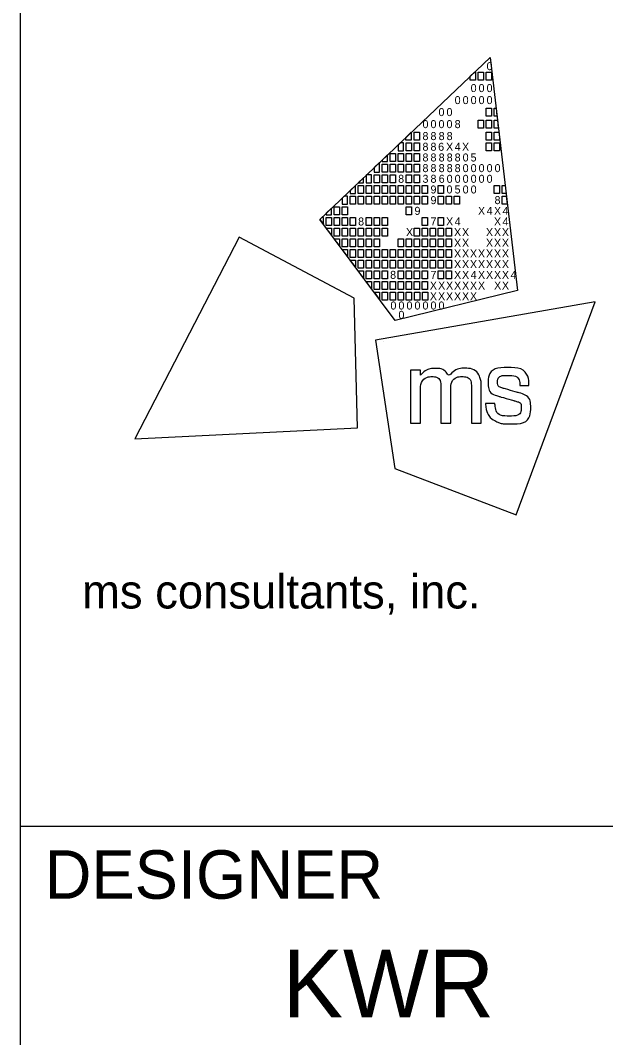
# Model space of a CAD drawing. Extents: x -0.2 to 34, y -3.5 to 18.5.
# Drawn here: x 32 to 33.207, y -1.472 to 0.627 of the extents above; entities that cross this region are included whole.
import ezdxf

# ---------------------------------------------------------------- set-up
doc = ezdxf.new("R2010")
doc.units = 0
doc.layers.add('SH_Border', color=7, linetype='Continuous')
doc.layers.add('SH_Data', color=7, linetype='Continuous')

msp = doc.modelspace()

# ---------------------------------------------------------------- linework, layer by layer
at = {"layer": 'SH_Border'}
for p, q in [((32, -3.0354), (32, 17.9646)), ((32, -1.0354), (33.5, -1.0354))]:
    msp.add_line(p, q, dxfattribs=at)
at = {"layer": 'SH_Data'}
for p, q in [((32.6175, 0.2165), (32.9688, 0.5507)), ((32.9688, 0.5507), (32.9688, 0.5507)), ((32.9688, 0.5507), (33.0253, 0.0697)), ((32.773, 0.0076), (32.6175, 0.2165)), ((33.0253, 0.0697), (32.773, 0.0076)), ((32.75, -0.0354), (32.75, -0.0354))]:
    msp.add_line(p, q, dxfattribs=at)
for points in [[(32.9279, 0.5118), (32.9369, 0.5203), (32.9389, 0.5203), (32.9389, 0.5038), (32.9279, 0.5038)], [(32.9444, 0.5203), (32.9554, 0.5203), (32.9554, 0.5038), (32.9444, 0.5038)], [(32.9609, 0.5203), (32.9719, 0.5203), (32.9719, 0.5038), (32.9609, 0.5038)], [(32.9606, 0.446), (32.9716, 0.446), (32.9716, 0.4295), (32.9606, 0.4295)], [(32.9771, 0.446), (32.9811, 0.446), (32.983, 0.4295), (32.9771, 0.4295)], [(32.9441, 0.4213), (32.9551, 0.4213), (32.9551, 0.4047), (32.9441, 0.4047)], [(32.9606, 0.4213), (32.9716, 0.4213), (32.9716, 0.4047), (32.9606, 0.4047)], [(32.9771, 0.4213), (32.984, 0.4213), (32.9859, 0.4047), (32.9771, 0.4047)], [(32.7953, 0.3857), (32.8064, 0.3961), (32.8064, 0.38), (32.7953, 0.38)], [(32.8123, 0.3965), (32.8233, 0.3965), (32.8233, 0.38), (32.8123, 0.38)], [(32.9606, 0.3965), (32.9716, 0.3965), (32.9716, 0.38), (32.9606, 0.38)], [(32.9771, 0.3965), (32.9869, 0.3965), (32.9881, 0.3864), (32.9881, 0.38), (32.9771, 0.38)], [(32.7958, 0.3745), (32.8068, 0.3745), (32.8068, 0.358), (32.7958, 0.358)], [(32.8123, 0.3745), (32.8233, 0.3745), (32.8233, 0.358), (32.8123, 0.358)], [(32.9606, 0.3745), (32.9716, 0.3745), (32.9716, 0.358), (32.9606, 0.358)], [(32.9771, 0.3745), (32.9881, 0.3745), (32.9881, 0.358), (32.9771, 0.358)], [(32.7627, 0.3524), (32.7737, 0.3524), (32.7737, 0.3359), (32.7627, 0.3359)], [(32.7793, 0.3524), (32.7903, 0.3524), (32.7903, 0.3359), (32.7793, 0.3359)], [(32.7958, 0.3524), (32.8068, 0.3524), (32.8068, 0.3359), (32.7958, 0.3359)], [(32.8123, 0.3524), (32.8233, 0.3524), (32.8233, 0.3359), (32.8123, 0.3359)], [(32.7462, 0.3304), (32.7572, 0.3304), (32.7572, 0.3139), (32.7462, 0.3139)], [(32.7627, 0.3304), (32.7737, 0.3304), (32.7737, 0.3139), (32.7627, 0.3139)], [(32.7793, 0.3304), (32.7903, 0.3304), (32.7903, 0.3139), (32.7793, 0.3139)], [(32.7958, 0.3304), (32.8068, 0.3304), (32.8068, 0.3139), (32.7958, 0.3139)], [(32.8123, 0.3304), (32.8233, 0.3304), (32.8233, 0.3139), (32.8123, 0.3139)], [(32.7297, 0.3084), (32.7407, 0.3084), (32.7407, 0.2919), (32.7297, 0.2919)], [(32.7462, 0.3084), (32.7572, 0.3084), (32.7572, 0.2919), (32.7462, 0.2919)], [(32.7627, 0.3084), (32.7737, 0.3084), (32.7737, 0.2919), (32.7627, 0.2919)], [(32.7958, 0.3084), (32.8068, 0.3084), (32.8068, 0.2919), (32.7958, 0.2919)], [(32.8123, 0.3084), (32.8233, 0.3084), (32.8233, 0.2919), (32.8123, 0.2919)], [(32.6967, 0.2864), (32.7077, 0.2864), (32.7077, 0.2699), (32.6967, 0.2699)], [(32.7132, 0.2864), (32.7242, 0.2864), (32.7242, 0.2699), (32.7132, 0.2699)], [(32.7297, 0.2864), (32.7407, 0.2864), (32.7407, 0.2699), (32.7297, 0.2699)], [(32.7462, 0.2864), (32.7572, 0.2864), (32.7572, 0.2699), (32.7462, 0.2699)], [(32.7627, 0.2864), (32.7737, 0.2864), (32.7737, 0.2699), (32.7627, 0.2699)], [(32.7793, 0.2864), (32.7903, 0.2864), (32.7903, 0.2699), (32.7793, 0.2699)], [(32.7958, 0.2864), (32.8068, 0.2864), (32.8068, 0.2699), (32.7958, 0.2699)], [(32.8123, 0.2864), (32.8233, 0.2864), (32.8233, 0.2699), (32.8123, 0.2699)], [(32.8288, 0.2864), (32.8398, 0.2864), (32.8398, 0.2699), (32.8288, 0.2699)], [(32.8618, 0.2864), (32.8728, 0.2864), (32.8728, 0.2699), (32.8618, 0.2699)], [(32.9771, 0.2864), (32.9881, 0.2864), (32.9881, 0.2699), (32.9771, 0.2699)], [(32.9935, 0.2864), (32.9998, 0.2864), (33.0018, 0.2699), (32.9935, 0.2699)], [(32.6802, 0.2644), (32.6912, 0.2644), (32.6912, 0.2479), (32.6802, 0.2479)], [(32.6967, 0.2644), (32.7077, 0.2644), (32.7077, 0.2479), (32.6967, 0.2479)], [(32.7132, 0.2644), (32.7242, 0.2644), (32.7242, 0.2479), (32.7132, 0.2479)], [(32.7297, 0.2644), (32.7407, 0.2644), (32.7407, 0.2479), (32.7297, 0.2479)], [(32.7462, 0.2644), (32.7572, 0.2644), (32.7572, 0.2479), (32.7462, 0.2479)], [(32.7627, 0.2644), (32.7737, 0.2644), (32.7737, 0.2479), (32.7627, 0.2479)], [(32.7793, 0.2644), (32.7903, 0.2644), (32.7903, 0.2479), (32.7793, 0.2479)], [(32.7958, 0.2644), (32.8068, 0.2644), (32.8068, 0.2479), (32.7958, 0.2479)], [(32.8123, 0.2644), (32.8233, 0.2644), (32.8233, 0.2479), (32.8123, 0.2479)], [(32.8288, 0.2644), (32.8398, 0.2644), (32.8398, 0.2479), (32.8288, 0.2479)], [(32.8618, 0.2644), (32.8728, 0.2644), (32.8728, 0.2479), (32.8618, 0.2479)], [(32.8783, 0.2644), (32.8893, 0.2644), (32.8893, 0.2479), (32.8783, 0.2479)], [(32.8947, 0.2644), (32.9057, 0.2644), (32.9057, 0.2479), (32.8947, 0.2479)], [(32.9935, 0.2644), (33.0024, 0.2644), (33.0044, 0.2479), (32.9935, 0.2479)], [(32.6471, 0.2424), (32.6581, 0.2424), (32.6581, 0.2258), (32.6471, 0.2258)], [(32.6637, 0.2424), (32.6747, 0.2424), (32.6747, 0.2258), (32.6637, 0.2258)], [(32.7958, 0.2424), (32.8068, 0.2424), (32.8068, 0.2258), (32.7958, 0.2258)], [(32.6306, 0.2203), (32.6416, 0.2203), (32.6416, 0.2038), (32.6306, 0.2038)], [(32.6471, 0.2203), (32.6581, 0.2203), (32.6581, 0.2038), (32.6471, 0.2038)], [(32.6637, 0.2203), (32.6747, 0.2203), (32.6747, 0.2038), (32.6637, 0.2038)], [(32.6802, 0.2203), (32.6912, 0.2203), (32.6912, 0.2038), (32.6802, 0.2038)], [(32.7132, 0.2203), (32.7242, 0.2203), (32.7242, 0.2038), (32.7132, 0.2038)], [(32.7297, 0.2203), (32.7407, 0.2203), (32.7407, 0.2038), (32.7297, 0.2038)], [(32.7462, 0.2203), (32.7572, 0.2203), (32.7572, 0.2038), (32.7462, 0.2038)], [(32.8288, 0.2203), (32.8398, 0.2203), (32.8398, 0.2038), (32.8288, 0.2038)], [(32.8618, 0.2203), (32.8728, 0.2203), (32.8728, 0.2038), (32.8618, 0.2038)], [(32.6306, 0.1983), (32.6416, 0.1983), (32.6416, 0.1846)], [(32.6471, 0.1983), (32.6581, 0.1983), (32.6581, 0.1818), (32.6471, 0.1818)], [(32.6637, 0.1983), (32.6747, 0.1983), (32.6747, 0.1818), (32.6637, 0.1818)], [(32.6802, 0.1983), (32.6912, 0.1983), (32.6912, 0.1818), (32.6802, 0.1818)], [(32.6967, 0.1983), (32.7077, 0.1983), (32.7077, 0.1818), (32.6967, 0.1818)], [(32.7132, 0.1983), (32.7242, 0.1983), (32.7242, 0.1818), (32.7132, 0.1818)], [(32.7297, 0.1983), (32.7407, 0.1983), (32.7407, 0.1818), (32.7297, 0.1818)], [(32.7462, 0.1983), (32.7572, 0.1983), (32.7572, 0.1818), (32.7462, 0.1818)], [(32.8123, 0.1983), (32.8233, 0.1983), (32.8233, 0.1818), (32.8123, 0.1818)], [(32.8288, 0.1983), (32.8398, 0.1983), (32.8398, 0.1818), (32.8288, 0.1818)], [(32.8453, 0.1983), (32.8563, 0.1983), (32.8563, 0.1818), (32.8453, 0.1818)], [(32.8618, 0.1983), (32.8728, 0.1983), (32.8728, 0.1818), (32.8618, 0.1818)], [(32.8783, 0.1983), (32.8893, 0.1983), (32.8893, 0.1818), (32.8783, 0.1818)], [(32.6471, 0.1763), (32.6581, 0.1763), (32.6581, 0.1625)], [(32.6637, 0.1763), (32.6747, 0.1763), (32.6747, 0.1598), (32.6637, 0.1598)], [(32.6802, 0.1763), (32.6912, 0.1763), (32.6912, 0.1598), (32.6802, 0.1598)], [(32.6967, 0.1763), (32.7077, 0.1763), (32.7077, 0.1598), (32.6967, 0.1598)], [(32.7132, 0.1763), (32.7242, 0.1763), (32.7242, 0.1598), (32.7132, 0.1598)], [(32.7297, 0.1763), (32.7407, 0.1763), (32.7407, 0.1598), (32.7297, 0.1598)], [(32.7793, 0.1763), (32.7903, 0.1763), (32.7903, 0.1598), (32.7793, 0.1598)], [(32.7958, 0.1763), (32.8068, 0.1763), (32.8068, 0.1598), (32.7958, 0.1598)], [(32.8123, 0.1763), (32.8233, 0.1763), (32.8233, 0.1598), (32.8123, 0.1598)], [(32.8288, 0.1763), (32.8398, 0.1763), (32.8398, 0.1598), (32.8288, 0.1598)], [(32.8453, 0.1763), (32.8563, 0.1763), (32.8563, 0.1598), (32.8453, 0.1598)], [(32.8618, 0.1763), (32.8728, 0.1763), (32.8728, 0.1598), (32.8618, 0.1598)], [(32.8783, 0.1763), (32.8893, 0.1763), (32.8893, 0.1598), (32.8783, 0.1598)], [(32.6637, 0.1543), (32.6747, 0.1543), (32.6747, 0.1405)], [(32.6747, 0.1543), (32.6747, 0.1543), (32.6747, 0.1543)], [(32.6802, 0.1543), (32.6912, 0.1543), (32.6912, 0.1378), (32.6802, 0.1378)], [(32.6967, 0.1543), (32.7077, 0.1543), (32.7077, 0.1378), (32.6967, 0.1378)], [(32.7132, 0.1543), (32.7242, 0.1543), (32.7242, 0.1378), (32.7132, 0.1378)], [(32.7297, 0.1543), (32.7407, 0.1543), (32.7407, 0.1378), (32.7297, 0.1378)], [(32.7462, 0.1543), (32.7572, 0.1543), (32.7572, 0.1378), (32.7462, 0.1378)], [(32.7627, 0.1543), (32.7737, 0.1543), (32.7737, 0.1378), (32.7627, 0.1378)], [(32.7793, 0.1543), (32.7903, 0.1543), (32.7903, 0.1378), (32.7793, 0.1378)], [(32.7958, 0.1543), (32.8068, 0.1543), (32.8068, 0.1378), (32.7958, 0.1378)], [(32.8123, 0.1543), (32.8233, 0.1543), (32.8233, 0.1378), (32.8123, 0.1378)], [(32.8288, 0.1543), (32.8398, 0.1543), (32.8398, 0.1378), (32.8288, 0.1378)], [(32.8453, 0.1543), (32.8563, 0.1543), (32.8563, 0.1378), (32.8453, 0.1378)], [(32.8618, 0.1543), (32.8728, 0.1543), (32.8728, 0.1378), (32.8618, 0.1378)], [(32.8783, 0.1543), (32.8893, 0.1543), (32.8893, 0.1378), (32.8783, 0.1378)], [(32.6802, 0.1323), (32.6912, 0.1323), (32.6912, 0.1185)], [(32.6967, 0.1323), (32.7077, 0.1323), (32.7077, 0.1158), (32.6967, 0.1158)], [(32.7132, 0.1323), (32.7242, 0.1323), (32.7242, 0.1158), (32.7132, 0.1158)], [(32.7297, 0.1323), (32.7407, 0.1323), (32.7407, 0.1158), (32.7297, 0.1158)], [(32.7462, 0.1323), (32.7572, 0.1323), (32.7572, 0.1158), (32.7462, 0.1158)], [(32.7627, 0.1323), (32.7737, 0.1323), (32.7737, 0.1158), (32.7627, 0.1158)], [(32.7793, 0.1323), (32.7903, 0.1323), (32.7903, 0.1158), (32.7793, 0.1158)], [(32.7958, 0.1323), (32.8068, 0.1323), (32.8068, 0.1158), (32.7958, 0.1158)], [(32.8123, 0.1323), (32.8233, 0.1323), (32.8233, 0.1158), (32.8123, 0.1158)], [(32.8288, 0.1323), (32.8398, 0.1323), (32.8398, 0.1158), (32.8288, 0.1158)], [(32.8453, 0.1323), (32.8563, 0.1323), (32.8563, 0.1158), (32.8453, 0.1158)], [(32.8618, 0.1323), (32.8728, 0.1323), (32.8728, 0.1158), (32.8618, 0.1158)], [(32.8783, 0.1323), (32.8893, 0.1323), (32.8893, 0.1158), (32.8783, 0.1158)], [(32.7077, 0.0951), (32.6965, 0.1103), (32.7077, 0.1103)], [(32.7132, 0.1102), (32.7242, 0.1102), (32.7242, 0.0937), (32.7132, 0.0937)], [(32.7297, 0.1102), (32.7407, 0.1102), (32.7407, 0.0937), (32.7297, 0.0937)], [(32.7462, 0.1102), (32.7572, 0.1102), (32.7572, 0.0937), (32.7462, 0.0937)], [(32.7793, 0.1102), (32.7903, 0.1102), (32.7903, 0.0937), (32.7793, 0.0937)], [(32.7958, 0.1102), (32.8068, 0.1102), (32.8068, 0.0937), (32.7958, 0.0937)], [(32.8123, 0.1102), (32.8233, 0.1102), (32.8233, 0.0937), (32.8123, 0.0937)], [(32.8288, 0.1102), (32.8398, 0.1102), (32.8398, 0.0937), (32.8288, 0.0937)], [(32.8618, 0.1102), (32.8728, 0.1102), (32.8728, 0.0937), (32.8618, 0.0937)], [(32.8783, 0.1102), (32.8893, 0.1102), (32.8893, 0.0937), (32.8783, 0.0937)], [(32.724, 0.0728), (32.7132, 0.0883), (32.7242, 0.0883)], [(32.7297, 0.0882), (32.7407, 0.0882), (32.7407, 0.0717), (32.7297, 0.0717)], [(32.7462, 0.0882), (32.7572, 0.0882), (32.7572, 0.0717), (32.7462, 0.0717)], [(32.7627, 0.0882), (32.7737, 0.0882), (32.7737, 0.0717), (32.7627, 0.0717)], [(32.7793, 0.0882), (32.7903, 0.0882), (32.7903, 0.0717), (32.7793, 0.0717)], [(32.7958, 0.0882), (32.8068, 0.0882), (32.8068, 0.0717), (32.7958, 0.0717)], [(32.8123, 0.0882), (32.8233, 0.0882), (32.8233, 0.0717), (32.8123, 0.0717)], [(32.8288, 0.0882), (32.8398, 0.0882), (32.8398, 0.0717), (32.8288, 0.0717)], [(32.7302, 0.0663), (32.7407, 0.0663), (32.7408, 0.0521)], [(32.7463, 0.0663), (32.7573, 0.0663), (32.7573, 0.0498), (32.7463, 0.0498)], [(32.763, 0.0663), (32.774, 0.0663), (32.774, 0.0498), (32.763, 0.0498)], [(32.7794, 0.0663), (32.7904, 0.0663), (32.7904, 0.0498), (32.7794, 0.0498)], [(32.796, 0.0663), (32.807, 0.0663), (32.807, 0.0498), (32.796, 0.0498)], [(32.8129, 0.0662), (32.8239, 0.0662), (32.8239, 0.0497), (32.8129, 0.0497)], [(32.8296, 0.0662), (32.8406, 0.0662), (32.8406, 0.0497), (32.8296, 0.0497)]]:
    msp.add_lwpolyline(points, close=True, dxfattribs=at)
for points in [[(32.7903, 0.3745), (32.7836, 0.3745), (32.7793, 0.3704), (32.7793, 0.358), (32.7903, 0.358), (32.7903, 0.3745)], [(32.7572, 0.3494), (32.7462, 0.3389), (32.7462, 0.3359), (32.7572, 0.3359), (32.7572, 0.3494)], [(32.7407, 0.3337), (32.7297, 0.3232), (32.7297, 0.3139), (32.7407, 0.3139), (32.7407, 0.3337)], [(32.7077, 0.3023), (32.6968, 0.2919), (32.7077, 0.2919), (32.7077, 0.3023)], [(32.7242, 0.3084), (32.7141, 0.3084), (32.7132, 0.3075), (32.7132, 0.2919), (32.7242, 0.2919), (32.7242, 0.3084)], [(32.6912, 0.2866), (32.6802, 0.2761), (32.6802, 0.2699), (32.6912, 0.2699), (32.6912, 0.2866)], [(32.6747, 0.2644), (32.6679, 0.2644), (32.6637, 0.2604), (32.6637, 0.2479), (32.6747, 0.2479), (32.6747, 0.2644)], [(32.6416, 0.2394), (32.6306, 0.229), (32.6306, 0.2258), (32.6416, 0.2258), (32.6416, 0.2394)], [(32.6251, 0.2203), (32.6216, 0.2203), (32.6175, 0.2165), (32.6251, 0.2063), (32.6251, 0.2203)], [(32.4512, 0.1794), (32.2359, -0.2367), (32.6956, -0.214), (32.6884, 0.0537), (32.4512, 0.1794)], [(33.0229, -0.3932), (33.1859, 0.046), (32.7324, -0.0325), (32.7722, -0.2973), (33.0229, -0.3932)]]:
    msp.add_lwpolyline(points, dxfattribs=at)
for points in [[(32.8048, -0.2039), (32.8048, -0.2039), (32.8048, -0.0945), (32.8048, -0.0945), (32.8048, -0.0945), (32.8255, -0.0945), (32.8255, -0.0945), (32.8255, -0.0945), (32.8255, -0.1057), (32.8255, -0.1057), (32.8346, -0.0955), (32.8457, -0.091), (32.8555, -0.091), (32.8688, -0.091), (32.8791, -0.0983), (32.8837, -0.1088), (32.8915, -0.0974), (32.905, -0.0908), (32.9166, -0.0908), (32.9325, -0.0908), (32.9451, -0.1004), (32.9494, -0.1142), (32.9494, -0.1142), (32.9494, -0.1143), (32.9494, -0.1143), (32.9501, -0.1165), (32.9506, -0.1182), (32.9506, -0.1284), (32.9506, -0.1284), (32.9506, -0.204), (32.9506, -0.204), (32.9506, -0.204), (32.9303, -0.204), (32.9303, -0.204), (32.9303, -0.204), (32.9303, -0.1307), (32.9303, -0.1307), (32.9303, -0.1153), (32.9219, -0.108), (32.911, -0.108), (32.8995, -0.108), (32.8879, -0.1184), (32.8879, -0.1353), (32.8879, -0.1353), (32.8879, -0.2039), (32.8879, -0.2039), (32.8879, -0.2039), (32.8674, -0.2039), (32.8674, -0.2039), (32.8674, -0.2039), (32.8674, -0.1295), (32.8674, -0.1295), (32.8674, -0.1151), (32.8588, -0.108), (32.8496, -0.108), (32.8384, -0.108), (32.8254, -0.1184), (32.8254, -0.1392), (32.8254, -0.1392), (32.8254, -0.2039), (32.8254, -0.2039), (32.8254, -0.2039), (32.8048, -0.2039), (32.8048, -0.2039)], [(32.9595, -0.1646), (32.9595, -0.1646), (32.9595, -0.1638), (32.9595, -0.1638), (32.9595, -0.1638), (32.9603, -0.1638), (32.9603, -0.1638), (32.9603, -0.1638), (32.9783, -0.1638), (32.9783, -0.1638), (32.9783, -0.1638), (32.9789, -0.1638), (32.9789, -0.1638), (32.9789, -0.1638), (32.979, -0.1645), (32.979, -0.1645), (32.9803, -0.18), (32.9887, -0.1894), (33.009, -0.1894), (33.0273, -0.1894), (33.0333, -0.18), (33.0333, -0.1723), (33.0333, -0.1623), (33.0256, -0.1597), (33.0175, -0.1574), (33.0175, -0.1574), (32.987, -0.1487), (32.987, -0.1487), (32.972, -0.1445), (32.9648, -0.1336), (32.9648, -0.1212), (32.9648, -0.1052), (32.9768, -0.0893), (33.0052, -0.0893), (33.0348, -0.0893), (33.0489, -0.107), (33.0489, -0.126), (33.0489, -0.126), (33.0489, -0.1267), (33.0489, -0.1267), (33.0489, -0.1267), (33.0482, -0.1267), (33.0482, -0.1267), (33.0482, -0.1267), (33.0312, -0.1267), (33.0312, -0.1267), (33.0312, -0.1267), (33.0305, -0.1267), (33.0305, -0.1267), (33.0305, -0.1267), (33.0305, -0.126), (33.0305, -0.126), (33.0301, -0.1146), (33.0226, -0.1055), (33.0056, -0.1055), (32.9891, -0.1055), (32.9843, -0.1137), (32.9843, -0.1197), (32.9843, -0.1247), (32.9869, -0.1295), (32.9959, -0.1321), (32.9959, -0.1321), (33.0255, -0.1406), (33.0255, -0.1406), (33.0462, -0.1466), (33.0527, -0.1577), (33.0527, -0.1715), (33.0527, -0.1892), (33.041, -0.2056), (33.0087, -0.2056), (32.9952, -0.2056), (32.9877, -0.2034), (32.9823, -0.2006), (32.969, -0.194), (32.9609, -0.1819), (32.9595, -0.1646)]]:
    msp.add_open_spline(points, degree=3, dxfattribs=at)

# ---------------------------------------------------------------- texts
for s, height, p in [('0', 0.0165, (32.9617, 0.5242)), ('0', 0.0165, (32.9288, 0.4791)), ('0', 0.0165, (32.9452, 0.4791)), ('0', 0.0165, (32.9617, 0.4791)), ('0', 0.0165, (32.8958, 0.4543)), ('0', 0.0165, (32.9123, 0.4543)), ('0', 0.0165, (32.9288, 0.4543)), ('0', 0.0165, (32.9452, 0.4543)), ('0', 0.0165, (32.9617, 0.4543)), ('0', 0.0165, (32.8625, 0.4295)), ('0', 0.0165, (32.879, 0.4295)), ('0', 0.0165, (32.8295, 0.4047)), ('0', 0.0165, (32.846, 0.4047)), ('0', 0.0165, (32.8625, 0.4047)), ('0', 0.0165, (32.879, 0.4047)), ('8', 0.0165, (32.8958, 0.4047)), ('8', 0.0165, (32.8295, 0.38)), ('8', 0.0165, (32.846, 0.38)), ('8', 0.0165, (32.8628, 0.38)), ('8', 0.0165, (32.8793, 0.38)), ('8', 0.0165, (32.8295, 0.358)), ('8', 0.0165, (32.846, 0.358)), ('6', 0.0165, (32.8618, 0.358)), ('X', 0.0165, (32.8781, 0.358)), ('4', 0.0165, (32.8958, 0.358)), ('X', 0.0165, (32.911, 0.358)), ('8', 0.0165, (32.8295, 0.3359)), ('8', 0.0165, (32.846, 0.3359)), ('8', 0.0165, (32.8628, 0.3359)), ('8', 0.0165, (32.8794, 0.3359)), ('8', 0.0165, (32.8958, 0.3359)), ('0', 0.0165, (32.9123, 0.3359)), ('5', 0.0165, (32.9287, 0.3359)), ('8', 0.0165, (32.8295, 0.3139)), ('8', 0.0165, (32.846, 0.3139)), ('8', 0.0165, (32.8628, 0.3139)), ('8', 0.0165, (32.8794, 0.3139)), ('8', 0.0165, (32.8958, 0.3139)), ('0', 0.0165, (32.9123, 0.3139)), ('0', 0.0165, (32.9288, 0.3139)), ('0', 0.0165, (32.9452, 0.3139)), ('0', 0.0165, (32.9617, 0.3139)), ('0', 0.0165, (32.9782, 0.3139)), ('8', 0.0165, (32.7793, 0.2919)), ('3', 0.0165, (32.8295, 0.2919)), ('8', 0.0165, (32.846, 0.2919)), ('6', 0.0165, (32.8629, 0.2919)), ('0', 0.0165, (32.8793, 0.2919)), ('0', 0.0165, (32.8958, 0.2919)), ('0', 0.0165, (32.9123, 0.2919)), ('0', 0.0165, (32.9288, 0.2919)), ('0', 0.0165, (32.9452, 0.2919)), ('0', 0.0165, (32.9617, 0.2919)), ('9', 0.0165, (32.846, 0.2699)), ('0', 0.0165, (32.879, 0.2699)), ('5', 0.0165, (32.8957, 0.2699)), ('0', 0.0165, (32.9123, 0.2699)), ('0', 0.0165, (32.9288, 0.2699)), ('9', 0.0165, (32.846, 0.2479)), ('8', 0.0165, (32.9781, 0.2479)), ('9', 0.0165, (32.813, 0.2258)), ('X', 0.0165, (32.9439, 0.2258)), ('4', 0.0165, (32.9617, 0.2258)), ('X', 0.0165, (32.9769, 0.2258)), ('4', 0.0165, (32.9946, 0.2258)), ('8', 0.0165, (32.6967, 0.2038)), ('7', 0.0165, (32.846, 0.2038)), ('X', 0.0165, (32.8781, 0.2038)), ('4', 0.0165, (32.8958, 0.2038)), ('X', 0.0165, (32.9769, 0.2038)), ('4', 0.0165, (32.9946, 0.2038)), ('X', 0.0165, (32.7955, 0.1818)), ('X', 0.0165, (32.8945, 0.1818)), ('X', 0.0165, (32.911, 0.1818)), ('X', 0.0165, (32.9604, 0.1818)), ('X', 0.0165, (32.9769, 0.1818)), ('X', 0.0165, (32.9933, 0.1818)), ('X', 0.0165, (32.8945, 0.1598)), ('X', 0.0165, (32.911, 0.1598)), ('X', 0.0165, (32.9604, 0.1598)), ('X', 0.0165, (32.9769, 0.1598)), ('X', 0.0165, (32.9933, 0.1598)), ('X', 0.0165, (32.8945, 0.1378)), ('X', 0.0165, (32.911, 0.1378)), ('X', 0.0165, (32.9274, 0.1378)), ('X', 0.0165, (32.9439, 0.1378)), ('X', 0.0165, (32.9604, 0.1378)), ('X', 0.0165, (32.9769, 0.1378)), ('X', 0.0165, (32.9933, 0.1378)), ('X', 0.0165, (32.8945, 0.1158)), ('X', 0.0165, (32.911, 0.1158)), ('X', 0.0165, (32.9274, 0.1158)), ('X', 0.0165, (32.9439, 0.1158)), ('X', 0.0165, (32.9604, 0.1158)), ('X', 0.0165, (32.9769, 0.1158)), ('X', 0.0165, (32.9933, 0.1158)), ('8', 0.0165, (32.7627, 0.0937)), ('7', 0.0165, (32.846, 0.0937)), ('X', 0.0165, (32.8945, 0.0937)), ('X', 0.0165, (32.911, 0.0937)), ('4', 0.0165, (32.9288, 0.0937)), ('X', 0.0165, (32.9439, 0.0937)), ('X', 0.0165, (32.9604, 0.0937)), ('X', 0.0165, (32.9769, 0.0937)), ('X', 0.0165, (32.9933, 0.0937)), ('4', 0.0165, (33.0111, 0.0937)), ('X', 0.0165, (32.8447, 0.0717)), ('X', 0.0165, (32.8616, 0.0717)), ('X', 0.0165, (32.878, 0.0717)), ('X', 0.0165, (32.8945, 0.0717)), ('X', 0.0165, (32.911, 0.0717)), ('X', 0.0165, (32.9274, 0.0717)), ('X', 0.0165, (32.9439, 0.0717)), ('X', 0.0165, (32.9771, 0.0717)), ('X', 0.0165, (32.9933, 0.0717)), ('X', 0.0165, (32.8447, 0.0497)), ('X', 0.0165, (32.8616, 0.0497)), ('X', 0.0165, (32.878, 0.0497)), ('X', 0.0165, (32.8945, 0.0497)), ('X', 0.0165, (32.911, 0.0497)), ('X', 0.0165, (32.9274, 0.0497)), ('0', 0.0165, (32.7634, 0.0304)), ('0', 0.0165, (32.7799, 0.0304)), ('0', 0.0165, (32.7965, 0.0304)), ('0', 0.0165, (32.813, 0.0304)), ('0', 0.0165, (32.8295, 0.0304)), ('0', 0.0165, (32.846, 0.0304)), ('0', 0.0165, (32.8625, 0.0304)), ('0', 0.0165, (32.7799, 0.0112)), ('ms consultants, inc.', 0.07, (32.1273, -0.5865))]:
    msp.add_text(s, height=height, rotation=360, dxfattribs=at).set_placement(p)
for s, height, p in [('DESIGNER', 0.1, (32.05, -1.1854)), ('KWR', 0.14, (32.5407, -1.4304))]:
    msp.add_text(s, height=height, dxfattribs=at).set_placement(p)

doc.saveas('drawing.dxf')
